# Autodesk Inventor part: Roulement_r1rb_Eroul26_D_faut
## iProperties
Created: 2011-10
Part Number: Roulement_r1rb_Eroul26_D_faut
Document SubType Name: Modeling
Designer: Bruno
Author: Bruno
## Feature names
1. Base1
